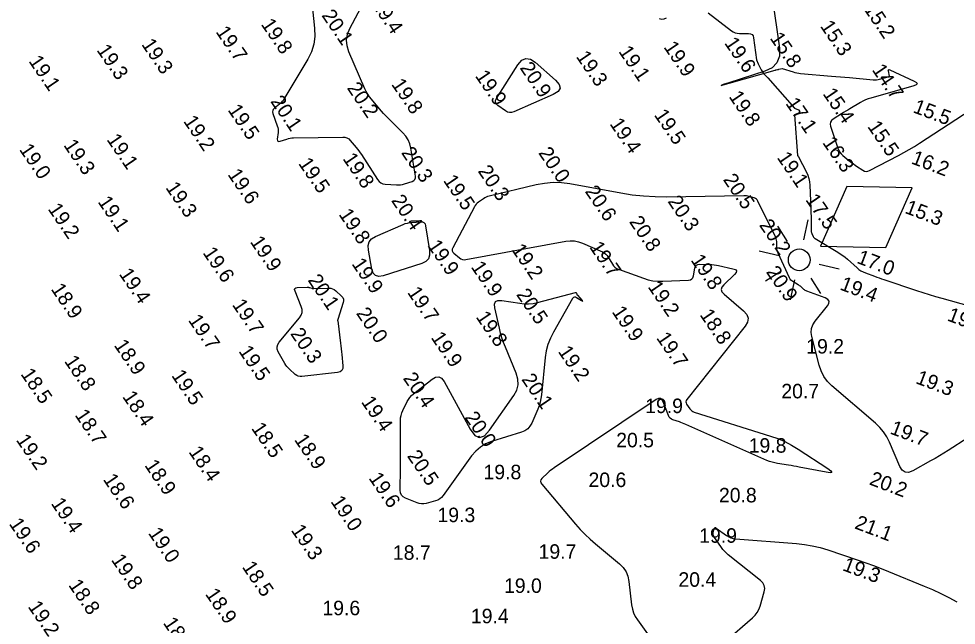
# Model space of a CAD drawing. Extents: x 824616 to 827440, y 158441 to 163197.
# Drawn here: x 826605.2 to 826928.3, y 159873.5 to 160082.7 of the extents above; entities that cross this region are included whole.
import ezdxf

# ---------------------------------------------------------------- set-up
doc = ezdxf.new("R2010")
doc.units = 0
for name, color, linetype in [('V-CHAN-CONT-EL16', 7, 'Continuous'), ('V-CHAN-CONT-EL18', 7, 'Continuous'), ('V-CHAN-CONT-EL20', 7, 'Continuous'), ('V-CHAN-NAID', 7, 'Continuous'), ('V-TOPO-SOUN', 7, 'Continuous'), ('V-TOPO-SOUN-EXSS', 7, 'Continuous')]:
    doc.layers.add(name, color=color, linetype=linetype)

msp = doc.modelspace()

# ---------------------------------------------------------------- linework, layer by layer
at = {"layer": 'V-CHAN-CONT-EL16'}
msp.add_lwpolyline([(826864.88, 160090.22), (826867.3, 160072.58), (826867.3, 160069.78), (826866.46, 160067.52), (826864.78, 160065.78), (826862.26, 160064.58), (826849.93, 160060.62), (826847.95, 160059.97), (826847.29, 160059.72), (826847.97, 160059.88), (826849.98, 160060.44), (826865.82, 160064.94), (826865.92, 160064.97), (826866.03, 160065), (826866.14, 160065.03), (826866.24, 160065.05), (826866.67, 160065.15), (826866.78, 160065.17), (826866.88, 160065.2), (826866.99, 160065.23), (826867.1, 160065.26), (826868.23, 160065.59), (826868.24, 160065.6), (826868.24, 160065.59), (826868.24, 160065.59), (826868.24, 160065.58), (826868.23, 160065.56), (826868.23, 160065.55), (826868.23, 160065.54), (826868.23, 160065.54), (826868.24, 160065.54), (826872.04, 160064.34), (826872.67, 160064.16), (826873.32, 160064.02), (826873.97, 160063.91), (826874.63, 160063.83), (826885.25, 160062.94), (826886.8, 160062.81), (826888.35, 160062.67), (826889.9, 160062.54), (826891.45, 160062.4), (826899.61, 160061.68), (826900.18, 160061.65), (826900.74, 160061.68), (826901.3, 160061.75), (826901.86, 160061.88), (826905.26, 160062.81), (826905.27, 160062.82), (826905.28, 160062.82), (826905.28, 160062.83), (826905.28, 160062.85), (826904.87, 160064.72), (826904.85, 160064.98), (826904.92, 160065.12), (826905.07, 160065.16), (826905.32, 160065.08), (826913.76, 160061.21), (826914.56, 160060.74), (826914.8, 160060.31), (826914.5, 160059.92), (826913.63, 160059.58), (826898.81, 160055.35), (826897.88, 160055.06), (826896.97, 160054.7), (826896.09, 160054.28), (826895.24, 160053.81), (826891.63, 160051.65), (826890.9, 160051.22), (826890.18, 160050.78), (826889.46, 160050.34), (826888.74, 160049.89), (826885.88, 160048.11), (826885.28, 160047.62), (826884.93, 160047.04), (826884.83, 160046.38), (826884.97, 160045.62), (826887.46, 160038.06), (826887.76, 160037.35), (826888.14, 160036.69), (826888.61, 160036.1), (826889.18, 160035.57), (826891.85, 160033.41), (826892.36, 160033), (826892.87, 160032.61), (826893.4, 160032.24), (826893.94, 160031.88), (826896.11, 160030.45), (826896.65, 160030.18), (826897.21, 160030.07), (826897.77, 160030.12), (826898.34, 160030.34), (826908.36, 160035.58), (826910.2, 160036.58), (826912.03, 160037.62), (826913.82, 160038.7), (826915.6, 160039.83), (826940.61, 160056.12)], dxfattribs=at)
at = {"layer": 'V-CHAN-CONT-EL18'}
for points in [[(826842.74, 160084.73), (826850.76, 160078.59), (826851.4, 160078.17), (826852.08, 160077.88), (826852.8, 160077.7), (826853.56, 160077.64), (826856.68, 160077.63), (826857.37, 160077.53), (826857.9, 160077.24), (826858.26, 160076.76), (826858.45, 160076.08), (826859.48, 160068.55), (826860.02, 160067.17), (826860.98, 160065.1), (826861.83, 160063.84), (826862.83, 160062.75)], [(826825.89, 160082.76), (826826.72, 160082.53), (826827.57, 160082.63), (826828.44, 160083.07)], [(826862.83, 160062.75), (826863.3, 160062.31), (826863.3, 160062.31), (826872.52, 160051.89), (826873.94, 160051.29), (826874.41, 160050.71), (826873.93, 160050.12), (826872.51, 160049.54), (826873.57, 160035.58), (826873.87, 160035.11), (826876.64, 160029.81), (826877.12, 160028.73), (826877.48, 160027.63), (826877.72, 160026.49), (826877.83, 160025.31), (826878.15, 160017.1), (826878.18, 160016.31), (826878.2, 160015.52), (826878.21, 160014.73), (826878.22, 160013.93), (826878.23, 160009.75), (826878.24, 160009.47), (826878.29, 160009.2), (826878.36, 160008.94), (826878.47, 160008.68), (826878.94, 160007.66), (826879.07, 160007.42), (826879.24, 160007.2), (826879.43, 160007.02), (826879.66, 160006.86), (826887.44, 160002.2), (826888.31, 160001.65), (826889.15, 160001.06), (826889.96, 160000.44), (826890.74, 159999.77), (826894.08, 159996.79), (826894.73, 159996.26), (826895.42, 159995.8), (826896.16, 159995.4), (826896.93, 159995.07), (826900.11, 159993.9), (826900.91, 159993.61), (826901.71, 159993.32), (826902.51, 159993.04), (826903.31, 159992.77), (826914.6, 159988.97), (826916.75, 159988.26), (826918.92, 159987.58), (826921.09, 159986.92), (826923.27, 159986.29), (826932.65, 159983.66)]]:
    msp.add_lwpolyline(points, dxfattribs=at)
at = {"layer": 'V-CHAN-CONT-EL20'}
for points in [[(826705.64, 160094.05), (826707.16, 160079.43), (826707.23, 160076.61), (826706.86, 160073.9), (826706.06, 160071.28), (826704.81, 160068.76), (826696.58, 160054.92), (826696.27, 160054.45), (826695.91, 160054.01), (826695.52, 160053.6), (826695.09, 160053.23), (826693.3, 160051.83), (826692.93, 160051.45), (826692.72, 160051.03), (826692.67, 160050.56), (826692.78, 160050.04), (826694.3, 160045.75), (826694.46, 160045.21), (826694.56, 160044.65), (826694.59, 160044.09), (826694.56, 160043.52), (826694.31, 160041.23), (826694.33, 160040.75), (826694.49, 160040.46), (826694.81, 160040.36), (826695.28, 160040.45), (826697.6, 160041.22), (826698.17, 160041.38), (826698.75, 160041.51), (826699.34, 160041.58), (826699.94, 160041.61), (826716.89, 160041.88), (826717.63, 160041.82), (826718.31, 160041.6), (826718.92, 160041.24), (826719.45, 160040.72), (826721.47, 160038.35), (826721.97, 160037.75), (826722.44, 160037.13), (826722.9, 160036.5), (826723.33, 160035.85), (826728.86, 160027.25), (826729.38, 160026.61), (826730, 160026.13), (826730.72, 160025.82), (826731.53, 160025.68), (826735.34, 160025.44), (826736.03, 160025.42), (826736.72, 160025.48), (826737.41, 160025.59), (826738.08, 160025.77), (826740.76, 160026.61), (826741.33, 160026.88), (826741.71, 160027.28), (826741.89, 160027.79), (826741.88, 160028.42), (826740.35, 160038.07), (826740, 160039.57), (826739.42, 160040.96), (826738.63, 160042.23), (826737.61, 160043.38), (826732.4, 160048.48), (826731.65, 160049.24), (826730.91, 160050.02), (826730.19, 160050.82), (826729.49, 160051.63), (826726.73, 160054.92), (826726.07, 160055.76), (826725.48, 160056.64), (826724.95, 160057.57), (826724.49, 160058.53), (826718.99, 160071.3), (826718.35, 160073.33), (826718.18, 160075.34), (826718.5, 160077.33), (826719.29, 160079.3), (826724.07, 160088.39)], [(826932.26, 159938.14), (826925.45, 159933.81), (826923.97, 159932.88), (826922.46, 159931.98), (826920.95, 159931.09), (826919.42, 159930.23), (826913.28, 159926.82), (826911.85, 159926.27), (826910.63, 159926.34), (826909.62, 159927.03), (826908.82, 159928.33), (826905.22, 159936.64), (826904.29, 159938.49), (826903.17, 159940.21), (826901.87, 159941.78), (826900.38, 159943.22), (826885.42, 159956.13), (826883.89, 159957.65), (826882.65, 159959.35), (826881.68, 159961.22), (826880.99, 159963.26), (826878.46, 159973.07), (826878.25, 159974.51), (826878.37, 159975.89), (826878.83, 159977.19), (826879.62, 159978.41), (826883.84, 159983.66), (826884.36, 159984.54), (826884.41, 159985.3), (826883.98, 159985.92), (826883.08, 159986.41), (826876.81, 159988.72), (826876.52, 159988.85), (826876.24, 159988.99), (826875.98, 159989.17), (826875.73, 159989.37), (826874.78, 159990.22), (826874.54, 159990.42), (826874.29, 159990.62), (826874.03, 159990.8), (826873.76, 159990.97), (826871.97, 159992.04), (826871.61, 159992.3), (826871.29, 159992.6), (826871.03, 159992.94), (826870.81, 159993.33), (826866.85, 160001.87), (826866.68, 160002.3), (826866.56, 160002.73), (826866.49, 160003.17), (826866.46, 160003.63), (826866.46, 160005.47), (826866.43, 160005.92), (826866.36, 160006.37), (826866.23, 160006.8), (826866.06, 160007.22), (826859.94, 160019.83), (826859.71, 160020.21), (826859.42, 160020.51), (826859.07, 160020.75), (826858.66, 160020.92), (826856.88, 160021.44), (826856.44, 160021.55), (826855.99, 160021.63), (826855.54, 160021.67), (826855.08, 160021.68), (826828.43, 160021.22), (826824.47, 160021.25), (826820.53, 160021.48), (826816.61, 160021.9), (826812.7, 160022.51), (826795.12, 160025.72), (826792.21, 160026.1), (826789.31, 160026.18), (826786.41, 160025.94), (826783.53, 160025.4), (826767.28, 160021.49), (826766.77, 160021.35), (826766.29, 160021.15), (826765.82, 160020.91), (826765.38, 160020.63), (826763.64, 160019.4), (826763.22, 160019.08), (826762.86, 160018.71), (826762.54, 160018.3), (826762.27, 160017.85), (826754.79, 160003.72), (826754.59, 160003.18), (826754.59, 160002.69), (826754.78, 160002.23), (826755.16, 160001.81), (826757.08, 160000.2), (826757.58, 159999.86), (826758.11, 159999.65), (826758.67, 159999.57), (826759.27, 159999.62), (826793.78, 160006), (826795.23, 160006.16), (826796.66, 160006.1), (826798.06, 160005.82), (826799.44, 160005.33), (826806.32, 160002.27), (826806.93, 160001.94), (826807.47, 160001.53), (826807.94, 160001.04), (826808.33, 160000.47), (826809.78, 159998.03), (826810.18, 159997.47), (826810.65, 159997), (826811.2, 159996.62), (826811.83, 159996.33), (826820.45, 159993.18), (826822.07, 159992.67), (826823.73, 159992.33), (826825.4, 159992.16), (826827.11, 159992.16), (826836.01, 159992.57), (826836.64, 159992.69), (826837.12, 159992.96), (826837.47, 159993.4), (826837.67, 159994), (826838.21, 159996.73), (826838.41, 159997.32), (826838.76, 159997.74), (826839.24, 159997.99), (826839.86, 159998.06), (826843.24, 159997.97), (826844.03, 159997.93), (826844.81, 159997.86), (826845.6, 159997.74), (826846.37, 159997.59), (826851.3, 159996.51), (826852.15, 159996.2), (826852.52, 159995.77), (826852.43, 159995.2), (826851.86, 159994.5), (826848.14, 159990.95), (826847.48, 159990.11), (826847.27, 159989.29), (826847.53, 159988.47), (826848.23, 159987.67), (826854.95, 159982), (826856.06, 159980.76), (826856.51, 159979.46), (826856.32, 159978.09), (826855.48, 159976.65), (826835.41, 159951.4), (826835.18, 159951.01), (826835.09, 159950.61), (826835.15, 159950.21), (826835.35, 159949.8), (826836.46, 159948.16), (826836.76, 159947.78), (826837.11, 159947.47), (826837.51, 159947.22), (826837.96, 159947.04), (826864.25, 159938.8), (826866.75, 159937.93), (826869.16, 159936.88), (826871.5, 159935.68), (826873.76, 159934.3), (826883.95, 159927.64), (826885.09, 159926.78), (826885.39, 159926.27), (826884.82, 159926.1), (826883.4, 159926.29), (826874.16, 159928.09), (826873.23, 159928.27), (826872.29, 159928.43), (826871.35, 159928.59), (826870.41, 159928.74), (826866.65, 159929.33), (826865.72, 159929.51), (826864.81, 159929.74), (826863.91, 159930.04), (826863.03, 159930.39), (826835.05, 159942.8), (826834.51, 159943.03), (826833.96, 159943.25), (826833.41, 159943.45), (826832.85, 159943.64), (826830.61, 159944.37), (826830.09, 159944.6), (826829.66, 159944.92), (826829.32, 159945.33), (826829.07, 159945.84), (826827.29, 159950.6), (826826.86, 159951.38), (826826.31, 159951.78), (826825.63, 159951.78), (826824.83, 159951.39), (826789.65, 159927.8), (826789.08, 159927.4), (826788.54, 159926.98), (826788.01, 159926.54), (826787.5, 159926.07), (826785.51, 159924.16), (826785.13, 159923.68), (826784.99, 159923.19), (826785.08, 159922.68), (826785.41, 159922.16), (826797.07, 159908.4), (826798.67, 159906.59), (826800.35, 159904.86), (826802.1, 159903.2), (826803.92, 159901.61), (826812.25, 159894.68), (826813.52, 159893.42), (826814.48, 159892), (826815.14, 159890.41), (826815.49, 159888.66), (826816.41, 159880.52), (826816.65, 159879.13), (826817.07, 159877.81), (826817.65, 159876.55), (826818.41, 159875.36), (826821.9, 159870.54)], [(826848.46, 159867.77), (826858.04, 159876.1), (826858.92, 159876.98), (826859.65, 159877.95), (826860.23, 159879.01), (826860.66, 159880.17), (826862.08, 159885.01), (826862.27, 159886.17), (826862.12, 159887.22), (826861.64, 159888.16), (826860.82, 159889), (826849.71, 159897.85), (826849.04, 159898.42), (826848.43, 159899.03), (826847.85, 159899.69), (826847.33, 159900.39), (826844.73, 159904.15), (826844.56, 159904.44), (826844.47, 159904.75), (826844.45, 159905.07), (826844.49, 159905.41), (826844.83, 159906.78), (826844.93, 159907.06), (826845.09, 159907.19), (826845.3, 159907.19), (826845.57, 159907.06), (826849.14, 159904.51), (826849.85, 159904.07), (826850.59, 159903.74), (826851.38, 159903.51), (826852.21, 159903.39), (826873.18, 159901.73), (826875.93, 159901.43), (826878.65, 159900.96), (826881.33, 159900.33), (826883.98, 159899.52), (826894.51, 159895.98), (826897.13, 159895.07), (826899.74, 159894.12), (826902.33, 159893.13), (826904.91, 159892.1), (826917.21, 159887.05), (826920.1, 159885.82), (826922.94, 159884.5), (826925.74, 159883.09), (826928.5, 159881.59)]]:
    msp.add_lwpolyline(points, dxfattribs=at)
for points in [[(826779.96, 160069.03), (826781.52, 160068.8), (826783.2, 160067.7), (826790.17, 160061.55), (826791.43, 160060.08), (826791.73, 160058.77), (826791.05, 160057.61), (826789.4, 160056.6), (826775.81, 160050.62), (826775.06, 160050.39), (826774.33, 160050.36), (826773.63, 160050.53), (826772.94, 160050.91), (826770.25, 160052.83), (826769.71, 160053.33), (826769.46, 160053.9), (826769.48, 160054.51), (826769.79, 160055.18), (826777.22, 160066.86), (826778.53, 160068.38)], [(826739.12, 160012.25), (826739.85, 160012.4), (826740.61, 160012.49), (826743.64, 160012.7), (826744.32, 160012.65), (826744.84, 160012.4), (826745.2, 160011.95), (826745.4, 160011.3), (826746.76, 160002.73), (826746.79, 160001.2), (826746.35, 159999.96), (826745.44, 159999.01), (826744.06, 159998.34), (826730.73, 159994.08), (826729.3, 159993.84), (826728.19, 159994.14), (826727.39, 159994.98), (826726.92, 159996.35), (826725.68, 160002.92), (826725.6, 160004.45), (826725.98, 160005.73), (826726.82, 160006.76), (826728.12, 160007.56), (826737.7, 160011.77), (826738.4, 160012.04)], [(826715.1, 159978.75), (826715.1, 159978.63), (826715.11, 159978.51), (826716.1, 159970.83), (826716.23, 159969.85), (826716.34, 159968.86), (826716.44, 159967.88), (826716.53, 159966.89), (826716.89, 159962.95), (826716.84, 159962.07), (826716.53, 159961.41), (826715.95, 159960.97), (826715.1, 159960.75), (826702.76, 159959.33), (826702.13, 159959.32), (826701.53, 159959.43), (826700.98, 159959.68), (826700.47, 159960.05), (826698.51, 159961.8), (826698.04, 159962.26), (826697.61, 159962.75), (826697.23, 159963.27), (826696.88, 159963.83), (826694.63, 159967.87), (826694.29, 159968.72), (826694.23, 159969.55), (826694.44, 159970.35), (826694.94, 159971.12), (826701.96, 159979.55), (826702.55, 159980.46), (826702.86, 159981.42), (826702.86, 159982.43), (826702.57, 159983.49), (826700.41, 159988.76), (826700.28, 159989.28), (826700.37, 159989.66), (826700.67, 159989.9), (826701.2, 159989.99), (826704.64, 159990.11), (826704.84, 159990.11), (826705.03, 159990.09), (826705.22, 159990.06), (826705.41, 159990.01), (826706.16, 159989.77), (826706.35, 159989.71), (826706.54, 159989.68), (826706.73, 159989.66), (826706.93, 159989.65), (826712.11, 159989.78), (826712.76, 159989.73), (826713.37, 159989.57), (826713.93, 159989.29), (826714.45, 159988.89), (826716.44, 159987.06), (826716.85, 159986.58), (826717.08, 159986.05), (826717.14, 159985.47), (826717.02, 159984.85), (826715.15, 159979), (826715.12, 159978.88)], [(826750.28, 159917.11), (826749.6, 159916.72), (826748.83, 159916.44), (826745.61, 159915.56), (826744.81, 159915.41), (826744.01, 159915.39), (826743.23, 159915.51), (826742.45, 159915.76), (826738.45, 159917.39), (826737.65, 159917.84), (826737.07, 159918.45), (826736.73, 159919.22), (826736.62, 159920.14), (826736.7, 159927.72), (826736.72, 159929.31), (826736.73, 159930.91), (826736.73, 159932.5), (826736.74, 159934.1), (826736.76, 159944.22), (826736.81, 159945.09), (826736.96, 159945.93), (826737.2, 159946.74), (826737.54, 159947.54), (826739.08, 159950.68), (826739.51, 159951.43), (826740, 159952.12), (826740.58, 159952.76), (826741.22, 159953.33), (826747.62, 159958.41), (826748.85, 159959.13), (826749.95, 159959.23), (826750.93, 159958.71), (826751.79, 159957.57), (826760.81, 159941.13), (826762.37, 159939.03), (826764, 159938.27), (826765.71, 159938.85), (826767.48, 159940.78), (826775.83, 159952.78), (826776.82, 159954.61), (826777.29, 159956.49), (826777.23, 159958.43), (826776.65, 159960.43), (826772.91, 159969.41), (826772.28, 159971.01), (826771.73, 159972.64), (826771.24, 159974.28), (826770.82, 159975.95), (826769.23, 159982.98), (826769.11, 159984.29), (826769.48, 159985.15), (826770.32, 159985.57), (826771.63, 159985.55), (826777.82, 159984.57), (826779.37, 159984.41), (826780.9, 159984.4), (826782.43, 159984.55), (826783.95, 159984.86), (826797.1, 159988.26), (826797.2, 159988.27), (826797.27, 159988.24), (826797.33, 159988.19), (826797.37, 159988.11), (826797.49, 159987.71), (826797.53, 159987.61), (826797.57, 159987.52), (826797.63, 159987.44), (826797.69, 159987.36), (826799.31, 159985.59), (826799.52, 159985.34), (826799.56, 159985.22), (826799.44, 159985.25), (826799.16, 159985.41), (826797.4, 159986.51), (826797.01, 159986.69), (826796.66, 159986.69), (826796.35, 159986.53), (826796.08, 159986.19), (826789.46, 159974.67), (826788.39, 159972.58), (826787.56, 159970.4), (826786.97, 159968.15), (826786.61, 159965.82), (826785.32, 159952.97), (826785.14, 159951.69), (826784.87, 159950.44), (826784.5, 159949.21), (826784.03, 159948.01), (826781.98, 159943.26), (826781.37, 159942.17), (826780.59, 159941.28), (826779.62, 159940.6), (826778.47, 159940.11), (826768.13, 159936.9), (826766.1, 159936.1), (826764.28, 159935), (826762.66, 159933.62), (826761.25, 159931.95), (826751.42, 159918.23), (826750.89, 159917.61)]]:
    msp.add_lwpolyline(points, close=True, dxfattribs=at)
at = {"layer": 'V-CHAN-NAID'}
for p, q in [((826875.68, 160006.45), (826877.2, 160013.33)), ((826870.13, 160005.87), (826866.78, 160011.13)), ((826860.38, 160002.61), (826867.26, 160001.09)), ((826881.04, 159998.03), (826887.92, 159996.51)), ((826867.84, 159995.54), (826862.58, 159992.19)), ((826878.17, 159993.25), (826881.52, 159987.99)), ((826871.1, 159985.79), (826872.62, 159992.67))]:
    msp.add_line(p, q, dxfattribs=at)
msp.add_lwpolyline([(826881.51, 160004.25), (826903.98, 160003.78), (826913.05, 160024.34), (826890.58, 160024.81)], close=True, dxfattribs=at)
msp.add_circle((826874.15, 159999.56), 3.74, dxfattribs=at)

# ---------------------------------------------------------------- texts
at = {"layer": 'V-TOPO-SOUN'}
for s, rotation, p in [('19.4 ', 304.2, (826726.55, 160087.7)), ('15.2 ', 304.2, (826896.17, 160086.14)), ('20.1 ', 304.2, (826709.42, 160083.86)), ('19.8 ', 304.2, (826688.52, 160080.8)), ('15.3 ', 304.2, (826881.19, 160080.16)), ('19.7 ', 304.2, (826672.92, 160078.21)), ('15.8 ', 304.2, (826863.87, 160076.03)), ('19.3 ', 304.2, (826647.32, 160073.88)), ('19.9 ', 304.2, (826827.25, 160072.96)), ('19.6 ', 304.2, (826848.17, 160074.35)), ('19.3 ', 304.2, (826631.89, 160071.9)), ('19.3 ', 304.2, (826797.07, 160069.65)), ('19.1 ', 304.2, (826811.72, 160071.42)), ('19.1 ', 304.2, (826608.45, 160068.08)), ('20.9 ', 304.2, (826777.7, 160065.76)), ('19.9 ', 304.2, (826762.3, 160062.99)), ('14.7 ', 304.2, (826899.05, 160065.1)), ('19.8 ', 304.2, (826733.43, 160060.11)), ('20.2 ', 304.2, (826718.15, 160058.82)), ('15.4 ', 304.2, (826882.09, 160056.84)), ('20.1 ', 304.2, (826691.79, 160054.21)), ('19.8 ', 304.2, (826849.71, 160055.87)), ('17.1 ', 304.2, (826869.26, 160053.51)), ('15.5 ', 339.2, (826913.05, 160050.51)), ('19.5 ', 304.2, (826677.07, 160051.24)), ('19.5 ', 304.2, (826823.97, 160049.53)), ('19.2 ', 304.2, (826661.77, 160047.37)), ('19.4 ', 304.2, (826808.66, 160046.47)), ('15.5 ', 304.2, (826897.48, 160045.53)), ('19.1 ', 304.2, (826635.33, 160041.05)), ('16.3 ', 304.2, (826881.98, 160039.99)), ('19.0 ', 304.2, (826605.21, 160037.62)), ('19.3 ', 304.2, (826620.46, 160039.13)), ('20.3 ', 304.2, (826736.85, 160036.49)), ('20.0 ', 304.2, (826784.11, 160036.43)), ('19.8 ', 304.2, (826716.66, 160034.46)), ('19.1 ', 304.2, (826866.3, 160034.83)), ('16.2 ', 339.2, (826912.44, 160032.86)), ('19.5 ', 304.2, (826701.38, 160032.8)), ('20.3 ', 304.2, (826763.25, 160030.16)), ('19.6 ', 304.2, (826677.02, 160029)), ('19.5 ', 304.2, (826751.32, 160026.91)), ('20.5 ', 304.2, (826847.73, 160027.24)), ('19.3 ', 304.2, (826655.62, 160024.46)), ('20.6 ', 304.2, (826800.15, 160023.16)), ('19.1 ', 304.2, (826632.27, 160019.58)), ('20.4 ', 304.2, (826733.4, 160020.01)), ('20.3 ', 304.2, (826828.66, 160019.71)), ('15.3 ', 339.2, (826910.25, 160015.79)), ('19.2 ', 304.2, (826615.09, 160017.1)), ('19.8 ', 304.2, (826715.29, 160015.24)), ('20.8 ', 304.2, (826815.39, 160012.68)), ('19.9 ', 304.2, (826684.74, 160005.79)), ('19.9 ', 304.2, (826745.87, 160004.49)), ('19.6 ', 304.2, (826668.43, 160002.01)), ('19.2 ', 304.2, (826774.84, 160003.1)), ('19.7 ', 304.2, (826801.7, 160003.9)), ('19.9 ', 304.2, (826719.75, 159998.18)), ('19.8 ', 304.2, (826836.58, 159999.48)), ('17.0 ', 339.2, (826893.69, 159998.56)), ('19.4 ', 304.2, (826639.6, 159994.68)), ('19.9 ', 304.2, (826760.87, 159997.1)), ('20.9 ', 304.2, (826862.54, 159995.4)), ('20.1 ', 304.2, (826704.64, 159992.54)), ('19.4 ', 339.2, (826887.86, 159989.39)), ('18.9 ', 304.2, (826616.13, 159989.47)), ('19.7 ', 304.2, (826738.93, 159988.31)), ('19.2 ', 304.2, (826821.8, 159990.27)), ('20.5 ', 304.2, (826776.48, 159987.6)), ('19.7 ', 304.2, (826678.57, 159984.07)), ('19.9 ', 304.2, (826809.4, 159981.65)), ('19.7 ', 304.3, (826663.42, 159978.74)), ('20.0 ', 304.2, (826721.31, 159981.12)), ('19.8 ', 304.2, (826762.55, 159979.86)), ('18.8 ', 304.2, (826839.7, 159980.62)), ('19.1 ', 339.2, (826924.84, 159978.72)), ('20.3 ', 304.2, (826698.63, 159974.09)), ('19.9 ', 304.2, (826747.06, 159972.76)), ('19.7 ', 304.2, (826824.74, 159972.63)), ('18.9 ', 304.2, (826637.85, 159970.11)), ('19.5 ', 304.2, (826680.79, 159968.04)), ('19.2 ', 304.2, (826790.87, 159967.93)), ('18.8 ', 304.2, (826620.72, 159964.62)), ('18.5 ', 304.2, (826605.7, 159960.17)), ('19.5 ', 304.2, (826657.65, 159959.68)), ('20.4 ', 304.2, (826737.45, 159958.72)), ('19.3 ', 339.2, (826913.98, 159957.07)), ('20.1 ', 304.2, (826778.29, 159958.34)), ('18.4 ', 304.2, (826640.75, 159952.38)), ('19.4 ', 304.2, (826723.04, 159950.55)), ('18.7 ', 304.2, (826624.35, 159946.04)), ('20.0 ', 304.2, (826758.68, 159945.22)), ('18.5 ', 304.2, (826685.17, 159941.49)), ('19.7 ', 339.2, (826905.13, 159939.71)), ('19.2 ', 304.2, (826604.11, 159937.44)), ('18.9 ', 304.2, (826699.98, 159937.52)), ('18.4 ', 304.2, (826663.57, 159933.34)), ('20.5 ', 304.2, (826738.86, 159931.92)), ('18.9 ', 304.2, (826648.38, 159928.69)), ('18.6 ', 304.2, (826634.09, 159923.82)), ('19.6 ', 304.2, (826725.63, 159924.27)), ('20.2 ', 339.2, (826898.01, 159922.16)), ('19.4 ', 304.2, (826616.14, 159915.54)), ('19.0 ', 304.2, (826712.51, 159916.21)), ('19.6 ', 304.2, (826601.68, 159908.53)), ('21.1 ', 339.2, (826892.95, 159907.01)), ('19.0 ', 304.2, (826649.64, 159905.3)), ('19.3 ', 304.2, (826698.88, 159906.31)), ('19.8 ', 304.2, (826636.89, 159896.09)), ('19.3 ', 339.2, (826888.76, 159892.58)), ('18.5 ', 304.2, (826681.99, 159893.64)), ('18.8 ', 304.2, (826622.14, 159887.4)), ('18.9 ', 304.2, (826669.3, 159884.28)), ('19.2 ', 304.2, (826608.19, 159879.97)), ('18.8 ', 304.2, (826654.78, 159874.32))]:
    msp.add_text(s, height=5, rotation=rotation, dxfattribs=at).set_placement(p)
for s, p in [('19.2 ', (826876.57, 159967.24)), ('20.7 ', (826867.98, 159951.79)), ('19.9 ', (826821.07, 159946.7)), ('20.5 ', (826811.08, 159934.9)), ('19.8 ', (826856.74, 159933.05)), ('19.8 ', (826765.36, 159923.88)), ('20.6 ', (826801.54, 159921.2)), ('20.8 ', (826846.49, 159915.91)), ('19.3 ', (826749.5, 159909.09)), ('19.9 ', (826839.68, 159901.98)), ('18.7 ', (826734.13, 159896.11)), ('19.7 ', (826784.34, 159896.46)), ('19.0 ', (826772.43, 159884.69)), ('20.4 ', (826832.52, 159886.81)), ('19.6 ', (826709.85, 159876.99)), ('19.4 ', (826761.03, 159874.23))]:
    msp.add_text(s, height=5, dxfattribs=at).set_placement(p)
at = {"layer": 'V-TOPO-SOUN-EXSS'}
for s, p in [('17.5 ', (826876.12, 160020.29)), ('20.2 ', (826860.19, 160011.54))]:
    msp.add_text(s, height=5, rotation=304.2, dxfattribs=at).set_placement(p)

doc.saveas('drawing.dxf')
